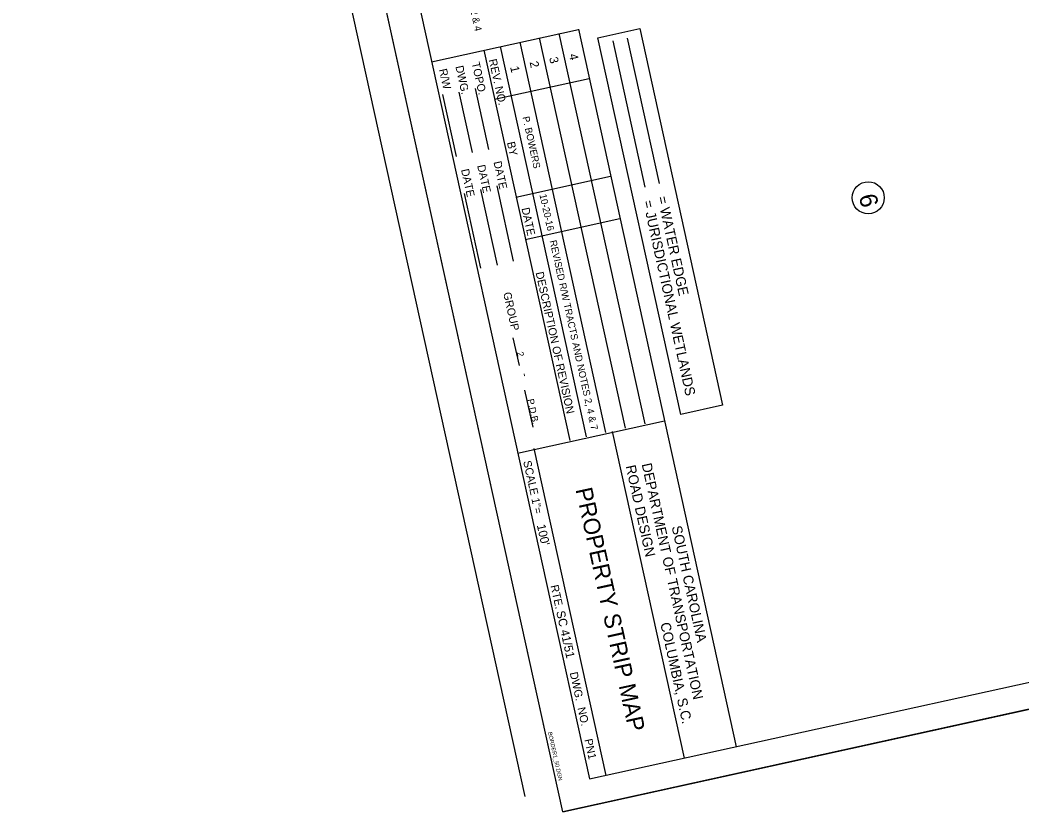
# Model space of a CAD drawing. Extents: x 2521558 to 2525396, y 882711 to 887632.
# Drawn here: x 2522393 to 2523894, y 882849 to 884035 of the extents above; entities that cross this region are included whole.
import ezdxf

# ---------------------------------------------------------------- set-up
doc = ezdxf.new("R2010")
doc.units = 0
for name, color, linetype in [('Default', 7, 'Continuous'), ('RD_EV_JW', 7, 'Continuous'), ('RD_EX_H2O', 7, 'Continuous'), ('RD_SHT_Bndy', 7, 'Continuous'), ('RD_SHT_IplotShp', 7, 'Continuous'), ('RD_SHT_Snap', 7, 'Continuous'), ('RD_SHT_TX', 7, 'Continuous'), ('RD_Sketch3', 7, 'Continuous'), ('RD_Sketch9', 7, 'Continuous')]:
    doc.layers.add(name, color=color, linetype=linetype)

msp = doc.modelspace()

# ---------------------------------------------------------------- linework, layer by layer
at = {"layer": 'Default'}
msp.add_lwpolyline([(2523321.3, 884022.6), (2523445.5, 883458.5), (2523382.8, 883444.7), (2523258.7, 884008.8)], close=True, dxfattribs=at)
at = {"layer": 'RD_EV_JW'}
msp.add_line((2523280.8, 884004.5), (2523329.1, 883785), dxfattribs=at)
at = {"layer": 'RD_EX_H2O'}
msp.add_line((2523350.8, 883790.4), (2523302.8, 884008.4), dxfattribs=at)
at = {"layer": 'RD_SHT_Bndy'}
for p, q in [((2523149.5, 882872.4), (2522392.6, 886310)), ((2523198.4, 882883.1), (2522441.4, 886320.8)), ((2522525.7, 886170.2), (2523246.2, 882898.6)), ((2523009.2, 883972.7), (2523229.3, 884021.2)), ((2523200, 884015.1), (2523328.7, 883430.4)), ((2523229.3, 884021.6), (2523465.9, 882946.9)), ((2523141.4, 884002.2), (2523270.1, 883417.5)), ((2523170.7, 884008.7), (2523299.4, 883423.9)), ((2523087.7, 883990.4), (2523216.4, 883405.6)), ((2523112.1, 883995.8), (2523240.8, 883411)), ((2523103.6, 883916.7), (2523245.4, 883947.9)), ((2523025.5, 883923.8), (2523046, 883830.8)), ((2523050.3, 883927.5), (2523070.2, 883837)), ((2523074.7, 883932.9), (2523094.8, 883841.6)), ((2523135.8, 883770.2), (2523277.6, 883801.4)), ((2523106.9, 883786.9), (2523131.6, 883674.4)), ((2523058.2, 883775.4), (2523082.8, 883663.6)), ((2523082.5, 883781.5), (2523107.4, 883668.1)), ((2523149.8, 883706.7), (2523291.6, 883738)), ((2523131.3, 883559.5), (2523140.5, 883517.7)), ((2523148.6, 883481), (2523160.9, 883425.4)), ((2523138.3, 883386.8), (2523358.3, 883435.2)), ((2523280, 883419.2), (2523387.8, 882929.7)), ((2523162.8, 883393.4), (2523270.6, 882903.9)), ((2523246.2, 882898.6), (2525297, 883350.2))]:
    msp.add_line(p, q, dxfattribs=at)
at = {"layer": 'RD_SHT_IplotShp'}
msp.add_lwpolyline([(2524581.9, 886830.2), (2525354.4, 883322.2), (2523205.9, 882849.1), (2522433.4, 886357.1)], close=True, dxfattribs=at)
at = {"layer": 'RD_SHT_Snap'}
msp.add_line((2523205.9, 882849.1), (2525354.4, 883322.2), dxfattribs=at)
at = {"layer": 'RD_Sketch3'}
msp.add_circle((2523663.8, 883769.2), 24, dxfattribs=at)

# ---------------------------------------------------------------- texts
at = {"layer": 'RD_EV_JW'}
for s, p in [('= WATER EDGE', (2523347.6, 883769.8)), ('= JURISDICTIONAL WETLANDS', (2523326.1, 883763.6))]:
    msp.add_text(s, height=15, rotation=282.4139, dxfattribs=at).set_placement(p)
at = {"layer": 'RD_SHT_TX'}
for s, height, p in [('4', 13, (2523215.1, 883983.6)), ('DWG.', 12, (2523045, 883965.8)), ('TOPO.', 12, (2523069.4, 883971.1)), ('REV. NO.', 12, (2523095, 883975.8)), ('2', 13, (2523156.2, 883972.2)), ('3', 13, (2523185.5, 883978.7)), ('R/W', 12, (2523020.4, 883961.2)), ('1', 13, (2523127, 883965)), ('BY', 12, (2523122.2, 883851.9)), ('DATE', 12, (2523077.6, 883817.3)), ('DATE', 12, (2523102.1, 883822.7)), ('DATE', 12, (2523053.4, 883811.1)), ('DATE', 12, (2523144, 883753.2)), ('DESCRIPTION OF REVISION', 12, (2523165.2, 883657)), ('GROUP', 12, (2523116.6, 883626.5)), ('2', 10, (2523137, 883537.5)), ('-', 12, (2523143.3, 883505.4)), ('P.D.B.', 10, (2523152.6, 883466.8)), ('SCALE 1"=', 12, (2523146.6, 883374.1)), ('ROAD DESIGN', 15, (2523300.1, 883367.1)), ('DEPARTMENT OF TRANSPORTATION', 15, (2523324.1, 883370)), ('PROPERTY STRIP MAP', 25, (2523224.9, 883332.3)), ("100'", 13, (2523167, 883278.7)), ('SOUTH CAROLINA', 15, (2523369.1, 883276.2)), ('RTE.', 12, (2523187.5, 883188)), ('SC 41/51', 13, (2523196, 883149.1)), ('COLUMBIA, S.C.', 15, (2523352, 883131.4)), ('DWG.', 12, (2523216.3, 883057.5)), ('NO.', 12, (2523227.9, 883004.8)), ('BORDER1_50.DGN', 6, (2523183.8, 882968.3)), ('PN1', 12, (2523238.3, 882957.4))]:
    msp.add_text(s, height=height, rotation=282.4185, dxfattribs=at).set_placement(p)
at = {"layer": 'RD_Sketch3'}
msp.add_text('6', height=26.4, rotation=282.6622, dxfattribs=at).set_placement((2523649.6, 883771.9))
at = {"layer": 'RD_Sketch9'}
for s, p in [('REVISED R/W TRACTS 2 & 4', (2523033.8, 884203)), ('P. BOWERS', (2523145.4, 883889.9)), ('10-20-16', (2523171, 883773.6)), ('REVISED R/W TRACTS AND NOTES 2, 4 & 7', (2523186.2, 883704.5))]:
    msp.add_text(s, height=10.5, rotation=282.4185, dxfattribs=at).set_placement(p)

doc.saveas('drawing.dxf')
